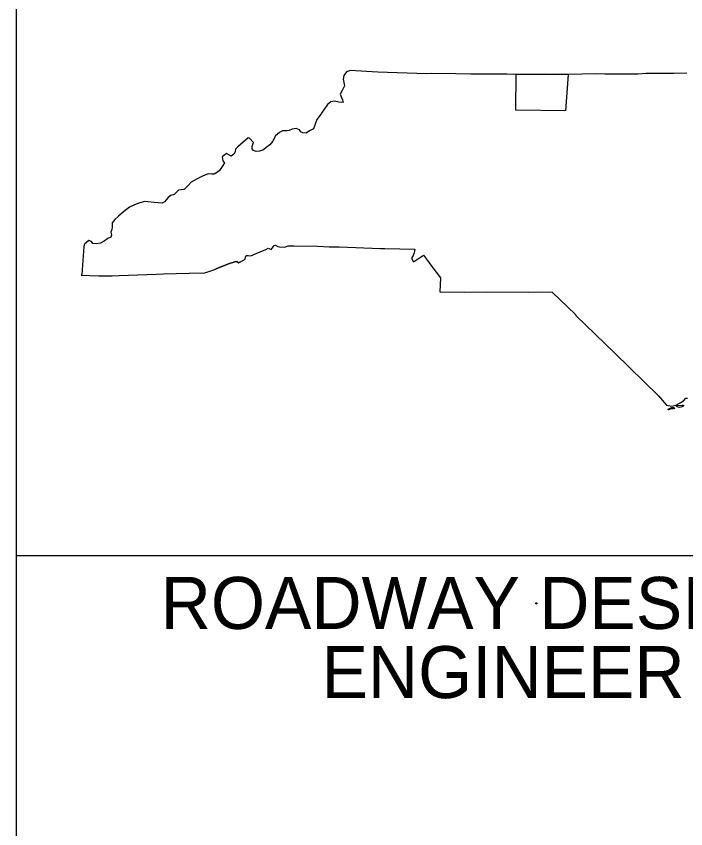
# Model space of a CAD drawing. Extents: x 1184121 to 1184397, y 1246506 to 1246661.
# Drawn here: x 1184344.34 to 1184353.41, y 1246638.07 to 1246649.06 of the extents above; entities that cross this region are included whole.
import ezdxf

# ---------------------------------------------------------------- set-up
doc = ezdxf.new("R2010")
doc.units = 0
for name, color, linetype in [('Old_Level_20', 7, 'Continuous'), ('P_RDY_Dimension_Text', 7, 'Continuous'), ('Sheet Plan CELL', 7, 'Continuous')]:
    doc.layers.add(name, color=color, linetype=linetype)

msp = doc.modelspace()

# ---------------------------------------------------------------- linework, layer by layer
at = {"layer": 'Old_Level_20'}
for points in [[(1184353.423, 1246648.29), (1184353.248, 1246648.288), (1184352.873, 1246648.287), (1184352.761, 1246648.28), (1184352.31, 1246648.278), (1184352.186, 1246648.282), (1184351.814, 1246648.274), (1184351.507, 1246648.278), (1184351.074, 1246648.273), (1184350.986, 1246648.279), (1184350.498, 1246648.28), (1184350.296, 1246648.284), (1184349.971, 1246648.287), (1184349.9, 1246648.285), (1184349.241, 1246648.304), (1184348.861, 1246648.329), (1184348.856, 1246648.324), (1184348.814, 1246648.308), (1184348.78, 1246648.26), (1184348.768, 1246648.213), (1184348.78, 1246648.167), (1184348.787, 1246648.122), (1184348.755, 1246648.057), (1184348.728, 1246648.006), (1184348.748, 1246647.963), (1184348.76, 1246647.932), (1184348.768, 1246647.894), (1184348.71, 1246647.898), (1184348.651, 1246647.914), (1184348.605, 1246647.904), (1184348.557, 1246647.866), (1184348.477, 1246647.751), (1184348.47, 1246647.744), (1184348.412, 1246647.663), (1184348.367, 1246647.541), (1184348.314, 1246647.51), (1184348.271, 1246647.482), (1184348.225, 1246647.486), (1184348.197, 1246647.499), (1184348.177, 1246647.527), (1184348.134, 1246647.542), (1184348.081, 1246647.533), (1184348.039, 1246647.515), (1184348.004, 1246647.512), (1184347.951, 1246647.511), (1184347.907, 1246647.49), (1184347.856, 1246647.442), (1184347.835, 1246647.412), (1184347.82, 1246647.372), (1184347.776, 1246647.323), (1184347.729, 1246647.285), (1184347.691, 1246647.253), (1184347.639, 1246647.238), (1184347.594, 1246647.234), (1184347.556, 1246647.246), (1184347.537, 1246647.268), (1184347.538, 1246647.3), (1184347.554, 1246647.356), (1184347.501, 1246647.412), (1184347.482, 1246647.415), (1184347.344, 1246647.297), (1184347.313, 1246647.264), (1184347.308, 1246647.226), (1184347.289, 1246647.194), (1184347.255, 1246647.171), (1184347.19, 1246647.204), (1184347.167, 1246647.186), (1184347.133, 1246647.161), (1184347.141, 1246647.104), (1184347.163, 1246647.079), (1184347.142, 1246647.043), (1184347.098, 1246646.973), (1184347.07, 1246646.954)], [(1184347.07, 1246646.954), (1184347.022, 1246646.925), (1184346.989, 1246646.925), (1184346.941, 1246646.93), (1184346.868, 1246646.899), (1184346.793, 1246646.862), (1184346.712, 1246646.817), (1184346.67, 1246646.774), (1184346.643, 1246646.743), (1184346.619, 1246646.719), (1184346.576, 1246646.714), (1184346.541, 1246646.711), (1184346.512, 1246646.682), (1184346.481, 1246646.651), (1184346.435, 1246646.635), (1184346.401, 1246646.61), (1184346.353, 1246646.55), (1184346.319, 1246646.535), (1184346.211, 1246646.543), (1184346.127, 1246646.553), (1184346.083, 1246646.554), (1184346.017, 1246646.538), (1184345.944, 1246646.51), (1184345.877, 1246646.477), (1184345.798, 1246646.417), (1184345.728, 1246646.356), (1184345.679, 1246646.314), (1184345.643, 1246646.266), (1184345.645, 1246646.215), (1184345.64, 1246646.175), (1184345.623, 1246646.141), (1184345.634, 1246646.102), (1184345.623, 1246646.074), (1184345.586, 1246646.053), (1184345.536, 1246646.017), (1184345.485, 1246645.99), (1184345.426, 1246645.981), (1184345.383, 1246645.989), (1184345.363, 1246646.016), (1184345.329, 1246646.027), (1184345.27, 1246645.978), (1184345.259, 1246645.945), (1184345.232, 1246645.569), (1184345.223, 1246645.559), (1184345.462, 1246645.549), (1184345.643, 1246645.552), (1184345.737, 1246645.554), (1184346.243, 1246645.572), (1184346.336, 1246645.577), (1184346.855, 1246645.592), (1184346.886, 1246645.584), (1184347.031, 1246645.634), (1184347.051, 1246645.645), (1184347.218, 1246645.714), (1184347.302, 1246645.74), (1184347.331, 1246645.744), (1184347.352, 1246645.727), (1184347.378, 1246645.737), (1184347.443, 1246645.776), (1184347.45, 1246645.802), (1184347.455, 1246645.826), (1184347.483, 1246645.823), (1184347.518, 1246645.821), (1184347.591, 1246645.852), (1184347.721, 1246645.904), (1184347.753, 1246645.923), (1184347.795, 1246645.907), (1184347.836, 1246645.959), (1184347.854, 1246645.964), (1184347.885, 1246645.945), (1184347.907, 1246645.942), (1184347.974, 1246645.938), (1184348.027, 1246645.956), (1184348.1, 1246645.954), (1184348.422, 1246645.952), (1184348.581, 1246645.944), (1184348.714, 1246645.942), (1184349.275, 1246645.918), (1184349.332, 1246645.921), (1184349.738, 1246645.91), (1184349.729, 1246645.86), (1184349.718, 1246645.823), (1184349.699, 1246645.799), (1184349.7, 1246645.778), (1184349.723, 1246645.74), (1184349.858, 1246645.828), (1184349.896, 1246645.774), (1184349.971, 1246645.676), (1184350.086, 1246645.523), (1184350.079, 1246645.333), (1184350.41, 1246645.328), (1184350.707, 1246645.333), (1184351.273, 1246645.331), (1184351.576, 1246645.333), (1184351.599, 1246645.331), (1184351.917, 1246645.026), (1184351.919, 1246645.014), (1184352.449, 1246644.504), (1184353.04, 1246643.925), (1184353.147, 1246643.802)], [(1184347.378, 1246645.737), (1184347.352, 1246645.727), (1184347.331, 1246645.744), (1184347.302, 1246645.74), (1184347.218, 1246645.714), (1184347.051, 1246645.645), (1184347.031, 1246645.634)], [(1184353.147, 1246643.802), (1184353.221, 1246643.786), (1184353.271, 1246643.8), (1184353.332, 1246643.831), (1184353.378, 1246643.86), (1184353.408, 1246643.896), (1184353.432, 1246643.896)], [(1184353.167, 1246643.743), (1184353.179, 1246643.751), (1184353.204, 1246643.762), (1184353.221, 1246643.766), (1184353.232, 1246643.767), (1184353.241, 1246643.766), (1184353.252, 1246643.763), (1184353.257, 1246643.761), (1184353.258, 1246643.758), (1184353.257, 1246643.756), (1184353.245, 1246643.749), (1184353.242, 1246643.75), (1184353.24, 1246643.753), (1184353.229, 1246643.75), (1184353.206, 1246643.746), (1184353.186, 1246643.741), (1184353.175, 1246643.738), (1184353.171, 1246643.737), (1184353.168, 1246643.74), (1184353.167, 1246643.743)], [(1184353.299, 1246643.794), (1184353.36, 1246643.801), (1184353.372, 1246643.801), (1184353.378, 1246643.799), (1184353.376, 1246643.79), (1184353.367, 1246643.783), (1184353.341, 1246643.773), (1184353.322, 1246643.77), (1184353.29, 1246643.778), (1184353.282, 1246643.782), (1184353.287, 1246643.789), (1184353.301, 1246643.795)]]:
    msp.add_lwpolyline(points, dxfattribs=at)
at = {"layer": 'P_RDY_Dimension_Text'}
msp.add_lwpolyline([(1184351.781, 1246647.782), (1184351.108, 1246647.79), (1184351.113, 1246648.273), (1184351.523, 1246648.278), (1184351.814, 1246648.274)], close=True, dxfattribs=at)
at = {"layer": 'Sheet Plan CELL'}
for p, q in [((1184344.345, 1246508.875), (1184344.348, 1246657.364)), ((1184358.423, 1246641.759), (1184344.348, 1246641.759))]:
    msp.add_line(p, q, dxfattribs=at)
msp.add_circle((1184351.386, 1246641.117), 0.00845, dxfattribs=at)

# ---------------------------------------------------------------- texts
for s, height, p in [('ROADWAY DESIGN ', 0.70377, (1184346.3, 1246640.772)), ('ENGINEER', 0.7038, (1184348.477, 1246639.836))]:
    msp.add_text(s, height=height, rotation=0, dxfattribs=at).set_placement(p)

doc.saveas('drawing.dxf')
